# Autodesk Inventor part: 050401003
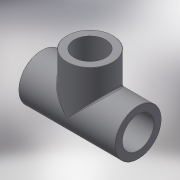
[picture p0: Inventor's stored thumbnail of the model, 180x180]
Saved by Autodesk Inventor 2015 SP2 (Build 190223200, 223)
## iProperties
Created: 2017-10
Part Number: 050401003
Material: Generic
Description: PLASSON THREADED TEE PVC 3/8"
Document SubType Name: Modeling
Designer: KIM
Density: 1 g/cm^3
Appearance: Default
Author: KIM
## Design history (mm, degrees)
derived "050401.ipt"
feature "Solid1::050401.ipt"
feature "Solid2::050401.ipt"
tag "TaggingFeature1"
body "Solid1"
other parameters: "d0" = 46, "d1" = 22, "d2" = 13, "d4" = 14.95, "d5" = 13.455, "d7" = 0.1495, "d8" = 13, "d9" = 23, "d10" = 22, "d15" = 0, "d18" = 14.95, "d24" = 0.1495, "d30" = 14.95, "d31" = 13, "d32" = 0, "d33" = 13.455, "d35" = 0, "d36" = 0.7475, "G_" = 14.95, "E_" = 22, "H_" = 46, "lt_" = 13
